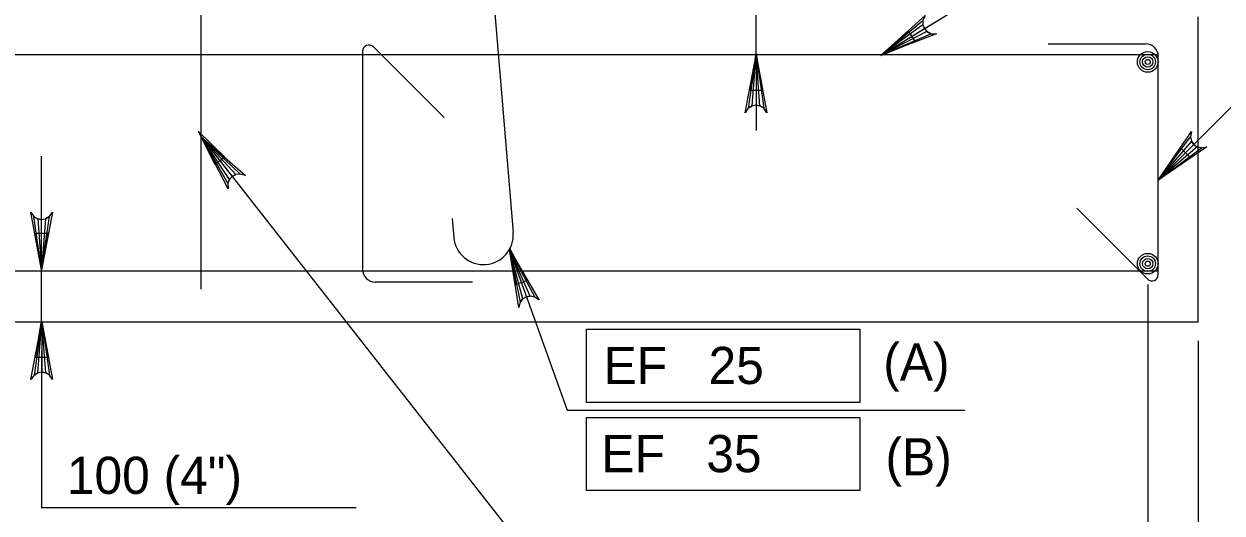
# Model space of a CAD drawing. Extents: x 634540 to 640306, y 296059 to 300275.
# Drawn here: x 639953.5 to 640050.2, y 297581 to 297620.4 of the extents above; entities that cross this region are included whole.
import ezdxf

# ---------------------------------------------------------------- set-up
doc = ezdxf.new("R2010")
doc.units = 0
for name, color, linetype in [('3', 7, 'Continuous'), ('4', 7, 'Continuous'), ('6', 7, 'Continuous'), ('9', 7, 'Continuous')]:
    doc.layers.add(name, color=color, linetype=linetype)

msp = doc.modelspace()

# ---------------------------------------------------------------- linework, layer by layer
at = {"layer": '4'}
for p, q in [((640022.677, 297617.923), (640041.884, 297629.687)), ((640012.557, 297617.923), (640012.557, 297626.898)), ((640012.557, 297614.781), (640012.557, 297611.829)), ((640045.019, 297607.828), (640051.101, 297613.891)), ((639967.778, 297611.312), (639997.355, 297573.577)), ((639992.648, 297602.216), (639997.309, 297589.253)), ((640044.167, 297599.405), (640044.167, 297553.643)), ((639998.882, 297595.782), (640020.922, 297595.782)), ((639998.882, 297589.876), (639998.882, 297595.782)), ((640020.922, 297595.782), (640020.922, 297589.876)), ((640048.232, 297594.855), (640048.232, 297536.84)), ((639954.903, 297594.059), (639954.903, 297581.365)), ((640020.922, 297589.876), (639998.882, 297589.876)), ((639997.309, 297589.253), (640029.421, 297589.253)), ((639998.882, 297588.669), (640020.922, 297588.669)), ((639998.882, 297582.763), (639998.882, 297588.669)), ((640020.922, 297588.669), (640020.922, 297582.763)), ((640020.922, 297582.763), (639998.882, 297582.763))]:
    msp.add_line(p, q, dxfattribs=at)
for points in [[(640022.677, 297617.923), (640026.195, 297621.102), (640026.018, 297620.702), (640026.023, 297620.339), (640026.141, 297620.044), (640026.35, 297619.806), (640026.671, 297619.637), (640027.108, 297619.612), (640022.677, 297617.923), (640026.671, 297619.637), (640026.35, 297619.806), (640022.677, 297617.923), (640026.141, 297620.044), (640026.023, 297620.339), (640022.677, 297617.923), (640026.018, 297620.702)], [(640012.557, 297617.923), (640013.43, 297613.262), (640013.182, 297613.62), (640012.87, 297613.806), (640012.557, 297613.86), (640012.245, 297613.806), (640011.932, 297613.62), (640011.684, 297613.262), (640012.557, 297617.923), (640011.932, 297613.62), (640012.245, 297613.806), (640012.557, 297617.923), (640012.557, 297613.86), (640012.87, 297613.806), (640012.557, 297617.923), (640013.182, 297613.62)], [(640045.019, 297607.828), (640047.703, 297611.737), (640047.624, 297611.308), (640047.713, 297610.956), (640047.896, 297610.697), (640048.155, 297610.514), (640048.507, 297610.422), (640048.936, 297610.499), (640045.019, 297607.828), (640048.507, 297610.422), (640048.155, 297610.514), (640045.019, 297607.828), (640047.896, 297610.697), (640047.713, 297610.956), (640045.019, 297607.828), (640047.624, 297611.308)], [(639967.778, 297611.312), (639971.341, 297608.183), (639970.924, 297608.312), (639970.564, 297608.266), (639970.285, 297608.114), (639970.072, 297607.878), (639969.941, 297607.541), (639969.966, 297607.106), (639967.778, 297611.312), (639969.941, 297607.541), (639970.072, 297607.878), (639967.778, 297611.312), (639970.285, 297608.114), (639970.564, 297608.266), (639967.778, 297611.312), (639970.924, 297608.312)], [(639954.903, 297600.572), (639954.03, 297605.233), (639954.278, 297604.874), (639954.59, 297604.689), (639954.903, 297604.635), (639955.215, 297604.689), (639955.528, 297604.874), (639955.776, 297605.233), (639954.903, 297600.572), (639955.528, 297604.874), (639955.215, 297604.689), (639954.903, 297600.572), (639954.903, 297604.635), (639954.59, 297604.689), (639954.903, 297600.572), (639954.278, 297604.874)], [(639992.648, 297602.216), (639995.048, 297598.126), (639994.692, 297598.38), (639994.336, 297598.449), (639994.023, 297598.393), (639993.746, 297598.236), (639993.515, 297597.957), (639993.402, 297597.534), (639992.648, 297602.216), (639993.515, 297597.957), (639993.746, 297598.236), (639992.648, 297602.216), (639994.023, 297598.393), (639994.336, 297598.449), (639992.648, 297602.216), (639994.692, 297598.38)], [(639954.915, 297596.393), (639955.79, 297591.732), (639955.54, 297592.09), (639955.228, 297592.276), (639954.915, 297592.33), (639954.603, 297592.276), (639954.29, 297592.09), (639954.042, 297591.732), (639954.915, 297596.393), (639954.29, 297592.09), (639954.603, 297592.276), (639954.915, 297596.393), (639954.915, 297592.33), (639955.228, 297592.276), (639954.915, 297596.393), (639955.54, 297592.09)]]:
    msp.add_lwpolyline(points, dxfattribs=at)
for points in [[(640025.398, 297619.01), (640024.883, 297619.85), (640022.622, 297617.887)], [(640013.049, 297615.043), (640012.064, 297615.043), (640012.557, 297617.998)], [(639968.891, 297609.093), (639969.685, 297609.674), (639967.543, 297611.764)], [(640047.557, 297609.664), (640046.863, 297610.362), (640045.119, 297607.928)], [(639993.136, 297599.405), (639994.069, 297599.718), (639992.663, 297602.359)], [(639955.394, 297593.517), (639954.411, 297593.517), (639954.903, 297596.47)]]:
    msp.add_lwpolyline(points, close=True, dxfattribs=at)
at = {"layer": '6'}
for p, q in [((639987.8, 297665.4), (639992.95, 297603.595)), ((639967.778, 297599.009), (639967.778, 297641.378)), ((639987.383, 297612.87), (639981.679, 297618.575)), ((640036.14, 297618.819), (640043.994, 297618.819)), ((640045.011, 297617.923), (639937.177, 297617.923)), ((639980.804, 297618.212), (639980.804, 297600.622)), ((640045.019, 297600.203), (640045.019, 297617.794)), ((639954.903, 297596.472), (639954.903, 297609.747)), ((640038.44, 297605.545), (640044.144, 297599.841)), ((639988.044, 297604.73), (639988.171, 297603.197)), ((639937.169, 297600.491), (640045.019, 297600.491)), ((639989.683, 297599.595), (639981.829, 297599.595)), ((639980.275, 297581.365), (639954.903, 297581.365))]:
    msp.add_line(p, q, dxfattribs=at)
msp.add_lwpolyline([(639954.411, 297603.526), (639955.394, 297603.526), (639954.903, 297600.572)], close=True, dxfattribs=at)
for centre, radius in [((640044.168, 297617.355), 0.833), ((640044.168, 297617.355), 0.625), ((640044.168, 297617.355), 0.417), ((640044.168, 297617.355), 0.208), ((640044.168, 297601.076), 0.833), ((640044.168, 297601.076), 0.625), ((640044.168, 297601.076), 0.417), ((640044.168, 297601.076), 0.208)]:
    msp.add_circle(centre, radius, dxfattribs=at)
for centre, radius, start, end in [((639981.316, 297618.212), 0.512, 45, 180), ((640043.994, 297617.794), 1.026, 0, 90), ((639990.562, 297603.397), 2.398, 184.76364, 4.76364), ((639981.829, 297600.622), 1.026, 180, 270), ((640044.507, 297600.203), 0.512, 225, 0)]:
    msp.add_arc(centre, radius, start, end, dxfattribs=at)
at = {"layer": '9'}
for p, q in [((640048.232, 297596.393), (640048.232, 297621)), ((639933.954, 297596.393), (640048.232, 297596.393))]:
    msp.add_line(p, q, dxfattribs=at)

# ---------------------------------------------------------------- texts
at = {"layer": '3'}
msp.add_text('100 (4")', height=3.0001, dxfattribs=at).set_placement((639956.936, 297582.494))
at = {"layer": '4'}
for s, p in [('EF   25', (640000.253, 297591.363)), ('(A)', (640022.827, 297591.636)), ('EF   35', (640000.071, 297584.248)), ('(B)', (640023.004, 297583.992))]:
    msp.add_text(s, height=3.0001, dxfattribs=at).set_placement(p)

doc.saveas('drawing.dxf')
